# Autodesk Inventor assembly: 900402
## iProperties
Created: 2007-10
Part Number: 900402
Document SubType Name: Assembly
Designer: TH
Mass: 85.0345 g
Surface Area: 363.511 cm^2
Volume: 33.1568 cm^3
Density: 2.56462 g/cm^3
Description: 1300 SERVO MOTOR
Component Category: Electrical
Author: TH
